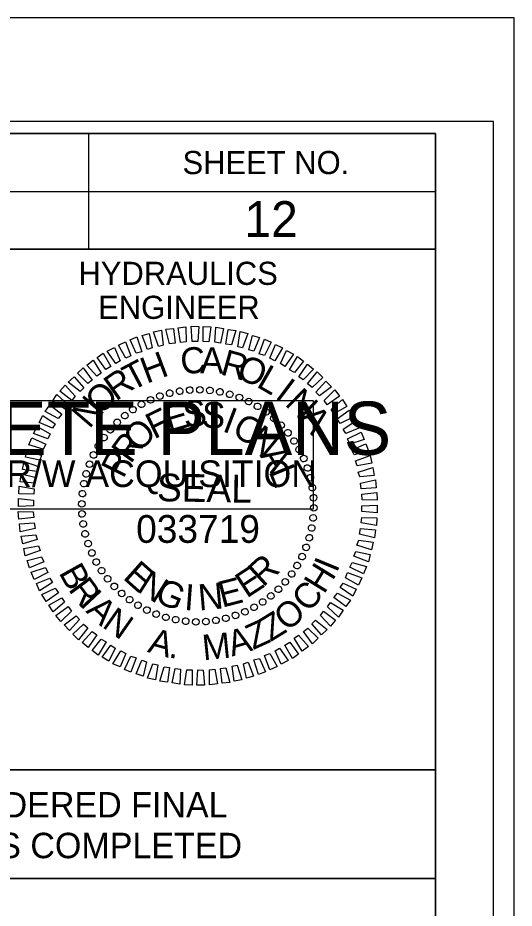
# Model space of a CAD drawing. Extents: x 1779926 to 1781610, y 620464 to 621564.
# Drawn here: x 1781502.7 to 1781610, y 621371.7 to 621564.2 of the extents above; entities that cross this region are included whole.
import ezdxf

# ---------------------------------------------------------------- set-up
doc = ezdxf.new("R2010")
doc.units = 0
for name, color, linetype in [('Old_Level_58', 7, 'Continuous'), ('Sheet Cutting Line CELL', 7, 'Continuous'), ('Sheet Data Field CELL', 7, 'Continuous'), ('Sheet Plot Border Inside CELL', 7, 'Continuous'), ('Sheet Plot Border Outside CELL', 7, 'Continuous'), ('Sheet Professional Seal CELL', 7, 'Continuous'), ('Sheet Profile CELL', 7, 'Continuous'), ('Sheet Profile Grid Major CELL', 7, 'Continuous'), ('Sheet Profile Grid Minor CELL', 7, 'Continuous'), ('Sheet Sticker Exception Certification CELL', 7, 'Continuous'), ('Sheet Sticker Incomplete CELL', 7, 'Continuous')]:
    doc.layers.add(name, color=color, linetype=linetype)

msp = doc.modelspace()

# ---------------------------------------------------------------- linework, layer by layer
at = {"layer": 'Old_Level_58'}
msp.add_lwpolyline([(1781392.96, 621378.14), (1781592.95, 621378.14), (1781592.95, 621314.19), (1781392.96, 621314.19)], close=True, dxfattribs=at)
at = {"layer": 'Sheet Cutting Line CELL'}
msp.add_line((1781609.96, 621564.19), (1779925.96, 621564.19), dxfattribs=at)
at = {"layer": 'Sheet Plot Border Inside CELL'}
msp.add_lwpolyline([(1779938.96, 620486.64), (1781605.46, 620486.64), (1781605.46, 621541.74), (1779938.96, 621541.74)], close=True, dxfattribs=at)
at = {"layer": 'Sheet Plot Border Outside CELL'}
msp.add_lwpolyline([(1779925.96, 620464.19), (1781609.96, 620464.19), (1781609.96, 621564.19), (1779925.96, 621564.19)], close=True, dxfattribs=at)
at = {"layer": 'Sheet Professional Seal CELL'}
for p, q in [((1781533.36, 621482.44), (1781533.36, 621482.44)), ((1781535.46, 621483.04), (1781535.46, 621483.04)), ((1781537.66, 621483.44), (1781537.66, 621483.44)), ((1781539.81, 621483.74), (1781539.81, 621483.74)), ((1781542.01, 621483.79), (1781542.01, 621483.79)), ((1781544.21, 621483.64), (1781544.21, 621483.64)), ((1781546.36, 621483.29), (1781546.36, 621483.29)), ((1781548.46, 621482.84), (1781548.46, 621482.84)), ((1781529.41, 621480.64), (1781529.41, 621480.64)), ((1781531.36, 621481.64), (1781531.36, 621481.64)), ((1781550.56, 621482.14), (1781550.56, 621482.14)), ((1781552.56, 621481.24), (1781552.56, 621481.24)), ((1781527.51, 621479.49), (1781527.51, 621479.49)), ((1781554.51, 621480.24), (1781554.51, 621480.24)), ((1781556.31, 621478.99), (1781556.31, 621478.99)), ((1781524.11, 621476.74), (1781524.11, 621476.74)), ((1781525.76, 621478.24), (1781525.76, 621478.24)), ((1781558.06, 621477.64), (1781558.06, 621477.64)), ((1781522.61, 621475.19), (1781522.61, 621475.19)), ((1781559.61, 621476.14), (1781559.61, 621476.14)), ((1781521.26, 621473.44), (1781521.26, 621473.44)), ((1781561.11, 621474.49), (1781561.11, 621474.49)), ((1781520.01, 621471.64), (1781520.01, 621471.64)), ((1781562.36, 621472.74), (1781562.36, 621472.74)), ((1781519.01, 621469.69), (1781519.01, 621469.69)), ((1781563.51, 621470.84), (1781563.51, 621470.84)), ((1781518.11, 621467.69), (1781518.11, 621467.69)), ((1781564.51, 621468.89), (1781564.51, 621468.89)), ((1781517.41, 621465.59), (1781517.41, 621465.59)), ((1781565.31, 621466.89), (1781565.31, 621466.89)), ((1781516.96, 621463.49), (1781516.96, 621463.49)), ((1781565.91, 621464.79), (1781565.91, 621464.79)), ((1781516.61, 621461.34), (1781516.61, 621461.34)), ((1781566.31, 621462.59), (1781566.31, 621462.59)), ((1781566.61, 621460.44), (1781566.61, 621460.44)), ((1781516.46, 621459.14), (1781516.46, 621459.14)), ((1781541.56, 621458.69), (1781541.56, 621458.69)), ((1781566.66, 621458.24), (1781566.66, 621458.24)), ((1781516.51, 621456.94), (1781516.51, 621456.94)), ((1781566.51, 621456.04), (1781566.51, 621456.04)), ((1781516.81, 621454.79), (1781516.81, 621454.79)), ((1781566.16, 621453.89), (1781566.16, 621453.89)), ((1781517.21, 621452.59), (1781517.21, 621452.59)), ((1781565.71, 621451.79), (1781565.71, 621451.79)), ((1781517.81, 621450.49), (1781517.81, 621450.49)), ((1781565.01, 621449.69), (1781565.01, 621449.69)), ((1781518.61, 621448.49), (1781518.61, 621448.49)), ((1781519.61, 621446.54), (1781519.61, 621446.54)), ((1781564.11, 621447.69), (1781564.11, 621447.69)), ((1781520.76, 621444.64), (1781520.76, 621444.64)), ((1781561.86, 621443.94), (1781561.86, 621443.94)), ((1781563.11, 621445.74), (1781563.11, 621445.74)), ((1781522.01, 621442.89), (1781522.01, 621442.89)), ((1781560.51, 621442.19), (1781560.51, 621442.19)), ((1781523.51, 621441.24), (1781523.51, 621441.24)), ((1781559.01, 621440.64), (1781559.01, 621440.64)), ((1781525.06, 621439.74), (1781525.06, 621439.74)), ((1781526.81, 621438.39), (1781526.81, 621438.39)), ((1781557.36, 621439.14), (1781557.36, 621439.14)), ((1781528.61, 621437.14), (1781528.61, 621437.14)), ((1781553.71, 621436.74), (1781553.71, 621436.74)), ((1781555.61, 621437.89), (1781555.61, 621437.89)), ((1781530.56, 621436.14), (1781530.56, 621436.14)), ((1781532.56, 621435.24), (1781532.56, 621435.24)), ((1781534.66, 621434.54), (1781534.66, 621434.54)), ((1781547.66, 621434.34), (1781547.66, 621434.34)), ((1781549.76, 621434.94), (1781549.76, 621434.94)), ((1781551.76, 621435.74), (1781551.76, 621435.74)), ((1781536.76, 621434.09), (1781536.76, 621434.09)), ((1781538.91, 621433.74), (1781538.91, 621433.74)), ((1781541.11, 621433.59), (1781541.11, 621433.59)), ((1781543.31, 621433.64), (1781543.31, 621433.64)), ((1781545.46, 621433.94), (1781545.46, 621433.94))]:
    msp.add_line(p, q, dxfattribs=at)
for points in [[(1781530.66, 621492.49), (1781529.51, 621495.49), (1781531.06, 621495.94), (1781531.71, 621492.84)], [(1781533.06, 621493.14), (1781532.01, 621496.29), (1781533.71, 621496.64), (1781534.11, 621493.39)], [(1781535.46, 621493.69), (1781534.66, 621496.89), (1781536.31, 621497.04), (1781536.66, 621493.84)], [(1781537.86, 621493.99), (1781537.31, 621497.19), (1781539.01, 621497.39), (1781539.06, 621494.14)], [(1781540.36, 621494.24), (1781540.11, 621497.49), (1781541.76, 621497.44), (1781541.56, 621494.19)], [(1781542.76, 621494.19), (1781542.76, 621497.44), (1781544.41, 621497.39), (1781543.96, 621494.14)], [(1781545.26, 621494.04), (1781545.46, 621497.29), (1781547.11, 621496.99), (1781546.46, 621493.84)], [(1781547.66, 621493.64), (1781548.11, 621496.84), (1781549.76, 621496.59), (1781548.86, 621493.49)], [(1781550.21, 621493.09), (1781550.71, 621496.34), (1781552.41, 621495.94), (1781551.26, 621492.84)], [(1781526.01, 621490.64), (1781524.41, 621493.44), (1781525.96, 621494.14), (1781527.11, 621491.09)], [(1781528.21, 621491.69), (1781526.91, 621494.59), (1781528.41, 621495.19), (1781529.46, 621491.99)], [(1781552.61, 621492.44), (1781553.36, 621495.54), (1781554.91, 621495.04), (1781553.66, 621492.09)], [(1781554.86, 621491.54), (1781556.01, 621494.69), (1781557.41, 621494.09), (1781556.01, 621491.19)], [(1781523.86, 621489.44), (1781522.01, 621492.14), (1781523.56, 621492.94), (1781524.81, 621490.04)], [(1781557.11, 621490.59), (1781558.36, 621493.54), (1781559.91, 621492.84), (1781558.21, 621490.04)], [(1781559.41, 621489.44), (1781560.76, 621492.29), (1781562.26, 621491.44), (1781560.36, 621488.84)], [(1781519.76, 621486.69), (1781517.61, 621489.09), (1781518.96, 621490.14), (1781520.71, 621487.34)], [(1781521.66, 621488.19), (1781519.81, 621490.74), (1781521.11, 621491.69), (1781522.76, 621488.79)], [(1781561.36, 621488.09), (1781563.11, 621490.99), (1781564.41, 621489.94), (1781562.46, 621487.49)], [(1781517.76, 621485.14), (1781515.56, 621487.34), (1781516.76, 621488.54), (1781518.71, 621485.84)], [(1781563.41, 621486.59), (1781565.26, 621489.34), (1781566.56, 621488.24), (1781564.36, 621485.89)], [(1781516.11, 621483.39), (1781513.56, 621485.44), (1781514.81, 621486.59), (1781516.91, 621484.19)], [(1781565.31, 621485.04), (1781567.36, 621487.64), (1781568.56, 621486.44), (1781566.26, 621484.29)], [(1781514.36, 621481.49), (1781511.76, 621483.44), (1781512.86, 621484.74), (1781515.06, 621482.39)], [(1781567.11, 621483.29), (1781569.26, 621485.64), (1781570.46, 621484.44), (1781567.86, 621482.49)], [(1781512.86, 621479.59), (1781510.16, 621481.29), (1781511.11, 621482.74), (1781513.51, 621480.54)], [(1781568.86, 621481.49), (1781571.16, 621483.74), (1781572.21, 621482.39), (1781569.56, 621480.49)], [(1781511.36, 621477.59), (1781508.56, 621479.09), (1781509.56, 621480.49), (1781512.16, 621478.49)], [(1781570.36, 621479.54), (1781572.81, 621481.64), (1781573.76, 621480.19), (1781570.96, 621478.59)], [(1781571.66, 621477.49), (1781574.31, 621479.39), (1781575.26, 621477.89), (1781572.36, 621476.49)], [(1781510.16, 621475.44), (1781507.31, 621476.69), (1781508.06, 621478.24), (1781510.76, 621476.39)], [(1781572.96, 621475.29), (1781575.76, 621477.04), (1781576.41, 621475.49), (1781573.56, 621474.34)], [(1781509.16, 621473.14), (1781506.06, 621474.29), (1781506.81, 621475.84), (1781509.66, 621474.24)], [(1781508.16, 621470.94), (1781505.06, 621471.84), (1781505.71, 621473.39), (1781508.71, 621471.99)], [(1781573.96, 621473.14), (1781576.91, 621474.64), (1781577.56, 621473.04), (1781574.46, 621472.04)], [(1781574.86, 621470.79), (1781577.91, 621472.09), (1781578.46, 621470.54), (1781575.36, 621469.74)], [(1781507.41, 621468.54), (1781504.31, 621469.19), (1781504.66, 621470.84), (1781507.81, 621469.59)], [(1781575.66, 621468.39), (1781578.86, 621469.54), (1781579.16, 621467.89), (1781576.01, 621467.34)], [(1781506.76, 621466.14), (1781503.66, 621466.54), (1781504.01, 621468.24), (1781507.16, 621467.19)], [(1781506.36, 621463.59), (1781503.16, 621463.89), (1781503.36, 621465.59), (1781506.61, 621464.79)], [(1781576.26, 621465.99), (1781579.41, 621466.94), (1781579.71, 621465.24), (1781576.56, 621464.94)], [(1781576.71, 621463.59), (1781579.96, 621464.29), (1781580.11, 621462.59), (1781576.91, 621462.39)], [(1781506.11, 621461.19), (1781502.86, 621461.29), (1781502.96, 621462.94), (1781506.21, 621462.39)], [(1781577.01, 621461.19), (1781580.26, 621461.59), (1781580.36, 621459.89), (1781577.11, 621459.99)], [(1781506.06, 621458.69), (1781502.81, 621458.54), (1781502.81, 621460.24), (1781506.06, 621459.89)], [(1781506.11, 621456.19), (1781502.86, 621455.79), (1781502.76, 621457.49), (1781506.01, 621457.39)], [(1781577.06, 621458.69), (1781580.31, 621458.84), (1781580.31, 621457.14), (1781577.06, 621457.49)], [(1781577.01, 621456.19), (1781580.26, 621456.09), (1781580.16, 621454.44), (1781576.91, 621454.99)], [(1781506.41, 621453.79), (1781503.16, 621453.09), (1781503.01, 621454.79), (1781506.21, 621454.99)], [(1781576.76, 621453.79), (1781579.96, 621453.49), (1781579.76, 621451.79), (1781576.51, 621452.59)], [(1781506.86, 621451.39), (1781503.71, 621450.44), (1781503.41, 621452.14), (1781506.56, 621452.44)], [(1781507.46, 621448.99), (1781504.26, 621447.84), (1781503.96, 621449.49), (1781507.11, 621450.04)], [(1781576.36, 621451.24), (1781579.46, 621450.84), (1781579.11, 621449.14), (1781575.96, 621450.19)], [(1781575.71, 621448.84), (1781578.81, 621448.19), (1781578.46, 621446.54), (1781575.31, 621447.79)], [(1781508.26, 621446.59), (1781505.21, 621445.29), (1781504.66, 621446.84), (1781507.76, 621447.64)], [(1781574.96, 621446.44), (1781578.06, 621445.54), (1781577.41, 621443.99), (1781574.41, 621445.39)], [(1781509.16, 621444.24), (1781506.21, 621442.74), (1781505.56, 621444.34), (1781508.66, 621445.34)], [(1781573.96, 621444.24), (1781577.06, 621443.09), (1781576.31, 621441.54), (1781573.46, 621443.14)], [(1781510.16, 621442.09), (1781507.36, 621440.34), (1781506.71, 621441.89), (1781509.56, 621443.04)], [(1781511.46, 621439.89), (1781508.81, 621437.99), (1781507.86, 621439.49), (1781510.76, 621440.89)], [(1781572.96, 621441.94), (1781575.81, 621440.69), (1781575.06, 621439.14), (1781572.36, 621440.99)], [(1781512.76, 621437.84), (1781510.31, 621435.74), (1781509.36, 621437.19), (1781512.16, 621438.79)], [(1781571.76, 621439.79), (1781574.56, 621438.29), (1781573.56, 621436.89), (1781570.96, 621438.89)], [(1781514.26, 621435.89), (1781511.96, 621433.64), (1781510.91, 621434.99), (1781513.56, 621436.89)], [(1781570.26, 621437.79), (1781572.96, 621436.09), (1781572.01, 621434.64), (1781569.61, 621436.84)], [(1781516.01, 621434.09), (1781513.86, 621431.74), (1781512.66, 621432.94), (1781515.26, 621434.89)], [(1781568.76, 621435.89), (1781571.36, 621433.94), (1781570.26, 621432.64), (1781568.06, 621434.99)], [(1781517.81, 621432.34), (1781515.76, 621429.74), (1781514.56, 621430.94), (1781516.86, 621433.09)], [(1781567.01, 621433.99), (1781569.56, 621431.94), (1781568.31, 621430.79), (1781566.21, 621433.19)], [(1781519.71, 621430.79), (1781517.86, 621428.04), (1781516.56, 621429.14), (1781518.76, 621431.49)], [(1781563.36, 621430.69), (1781565.51, 621428.29), (1781564.16, 621427.24), (1781562.41, 621430.04)], [(1781565.36, 621432.24), (1781567.56, 621430.04), (1781566.36, 621428.84), (1781564.41, 621431.54)], [(1781521.76, 621429.29), (1781520.01, 621426.39), (1781518.71, 621427.44), (1781520.66, 621429.89)], [(1781523.71, 621427.94), (1781522.36, 621425.09), (1781520.86, 621425.94), (1781522.76, 621428.54)], [(1781561.46, 621429.19), (1781563.31, 621426.64), (1781562.01, 621425.69), (1781560.36, 621428.59)], [(1781526.01, 621426.79), (1781524.76, 621423.84), (1781523.21, 621424.54), (1781524.91, 621427.34)], [(1781557.11, 621426.74), (1781558.71, 621423.94), (1781557.16, 621423.24), (1781556.01, 621426.29)], [(1781559.26, 621427.94), (1781561.11, 621425.24), (1781559.56, 621424.44), (1781558.31, 621427.34)], [(1781528.26, 621425.84), (1781527.11, 621422.69), (1781525.71, 621423.29), (1781527.11, 621426.19)], [(1781530.51, 621424.94), (1781529.76, 621421.84), (1781528.21, 621422.34), (1781529.46, 621425.29)], [(1781552.46, 621424.89), (1781553.61, 621421.89), (1781552.06, 621421.44), (1781551.41, 621424.54)], [(1781554.91, 621425.69), (1781556.21, 621422.79), (1781554.71, 621422.19), (1781553.66, 621425.39)], [(1781532.91, 621424.29), (1781532.41, 621421.04), (1781530.71, 621421.44), (1781531.86, 621424.54)], [(1781535.46, 621423.74), (1781535.01, 621420.54), (1781533.36, 621420.79), (1781534.26, 621423.89)], [(1781537.86, 621423.34), (1781537.66, 621420.09), (1781536.01, 621420.39), (1781536.66, 621423.54)], [(1781540.36, 621423.19), (1781540.36, 621419.94), (1781538.71, 621419.99), (1781539.16, 621423.24)], [(1781542.76, 621423.14), (1781543.01, 621419.89), (1781541.36, 621419.94), (1781541.56, 621423.19)], [(1781545.26, 621423.39), (1781545.81, 621420.19), (1781544.11, 621419.99), (1781544.06, 621423.24)], [(1781547.66, 621423.69), (1781548.46, 621420.49), (1781546.81, 621420.34), (1781546.46, 621423.54)], [(1781550.06, 621424.24), (1781551.11, 621421.09), (1781549.41, 621420.74), (1781549.01, 621423.99)]]:
    msp.add_lwpolyline(points, close=True, dxfattribs=at)
for centre, major_axis in [((1781539.81, 621483.71), (-0.05, 0.718)), ((1781542, 621483.77), (0.013, 0.72)), ((1781544.18, 621483.63), (0.075, 0.716)), ((1781531.36, 621481.6), (-0.293, 0.658)), ((1781533.39, 621482.4), (-0.234, 0.681)), ((1781535.49, 621483.03), (-0.174, 0.699)), ((1781537.64, 621483.46), (-0.113, 0.711)), ((1781546.34, 621483.31), (0.137, 0.707)), ((1781548.47, 621482.8), (0.198, 0.692)), ((1781550.55, 621482.1), (0.258, 0.672)), ((1781529.4, 621480.63), (-0.349, 0.63)), ((1781552.55, 621481.23), (0.316, 0.647)), ((1781554.48, 621480.19), (0.371, 0.617)), ((1781525.78, 621478.18), (-0.453, 0.56)), ((1781527.53, 621479.48), (-0.403, 0.597)), ((1781556.3, 621478.98), (0.423, 0.582)), ((1781524.14, 621476.73), (-0.5, 0.518)), ((1781558.01, 621477.62), (0.472, 0.543)), ((1781559.6, 621476.11), (0.518, 0.5)), ((1781522.63, 621475.14), (-0.543, 0.472)), ((1781561.05, 621474.47), (0.56, 0.453)), ((1781521.27, 621473.43), (-0.582, 0.423)), ((1781562.35, 621472.71), (0.597, 0.403)), ((1781520.06, 621471.61), (-0.617, 0.371)), ((1781563.49, 621470.85), (0.63, 0.349)), ((1781519.02, 621469.68), (-0.647, 0.316)), ((1781564.47, 621468.89), (0.658, 0.293)), ((1781518.15, 621467.68), (-0.672, 0.258)), ((1781565.27, 621466.86), (0.681, 0.234)), ((1781517.45, 621465.6), (-0.692, 0.198)), ((1781565.89, 621464.76), (0.699, 0.174)), ((1781516.94, 621463.48), (-0.707, 0.137)), ((1781566.33, 621462.61), (0.711, 0.113)), ((1781516.62, 621461.31), (-0.716, 0.075)), ((1781516.48, 621459.13), (-0.72, 0.013)), ((1781566.58, 621460.44), (0.718, 0.05)), ((1781516.54, 621456.94), (-0.718, -0.05)), ((1781566.64, 621458.25), (0.72, -0.013)), ((1781516.79, 621454.77), (-0.711, -0.113)), ((1781566.5, 621456.07), (0.716, -0.075)), ((1781566.18, 621453.9), (0.707, -0.137)), ((1781517.22, 621452.62), (-0.699, -0.174)), ((1781565.67, 621451.78), (0.692, -0.198)), ((1781517.85, 621450.52), (-0.681, -0.234)), ((1781564.97, 621449.7), (0.672, -0.258)), ((1781518.65, 621448.49), (-0.658, -0.293)), ((1781564.1, 621447.7), (0.647, -0.316)), ((1781519.62, 621446.53), (-0.63, -0.349)), ((1781563.06, 621445.77), (0.617, -0.371)), ((1781520.77, 621444.67), (-0.597, -0.403)), ((1781561.85, 621443.95), (0.582, -0.423)), ((1781522.07, 621442.91), (-0.56, -0.453)), ((1781523.52, 621441.27), (-0.518, -0.5)), ((1781560.49, 621442.24), (0.543, -0.472)), ((1781525.11, 621439.76), (-0.472, -0.543)), ((1781558.98, 621440.65), (0.5, -0.518)), ((1781526.82, 621438.4), (-0.423, -0.582)), ((1781555.58, 621437.9), (0.403, -0.597)), ((1781557.34, 621439.2), (0.453, -0.56)), ((1781528.64, 621437.19), (-0.371, -0.617)), ((1781530.56, 621436.15), (-0.316, -0.647)), ((1781551.76, 621435.78), (0.293, -0.658)), ((1781553.72, 621436.75), (0.349, -0.63)), ((1781532.57, 621435.28), (-0.258, -0.672)), ((1781534.65, 621434.58), (-0.198, -0.692)), ((1781536.77, 621434.07), (-0.137, -0.707)), ((1781538.94, 621433.75), (-0.075, -0.716)), ((1781541.12, 621433.61), (-0.013, -0.72)), ((1781543.31, 621433.67), (0.05, -0.718)), ((1781545.48, 621433.92), (0.113, -0.711)), ((1781547.63, 621434.36), (0.174, -0.699)), ((1781549.72, 621434.98), (0.234, -0.681))]:
    msp.add_ellipse(centre, major_axis=major_axis, ratio=0.999708, dxfattribs=at)
at = {"layer": 'Sheet Profile CELL'}
for p, q in [((1781517.96, 621539.14), (1781517.96, 621514.14)), ((1781392.91, 621526.64), (1781592.96, 621526.64))]:
    msp.add_line(p, q, dxfattribs=at)
for points in [[(1781592.96, 621539.19), (1780092.96, 621539.19), (1780092.96, 620489.19), (1781592.96, 620489.19)], [(1781392.91, 621539.19), (1781592.96, 621539.19), (1781592.96, 621514.14), (1781392.91, 621514.14)], [(1781492.96, 621514.14), (1781592.96, 621514.14), (1781592.96, 621401.64), (1781492.96, 621401.64)]]:
    msp.add_lwpolyline(points, close=True, dxfattribs=at)
at = {"layer": 'Sheet Profile Grid Major CELL'}
msp.add_lwpolyline([(1781542.96, 621314.19), (1781542.96, 621039.19), (1781592.96, 621039.19), (1781592.96, 621389.19)], dxfattribs=at)
at = {"layer": 'Sheet Sticker Exception Certification CELL'}
for p, q in [((1781392.91, 621401.64), (1781592.95, 621401.64)), ((1781392.91, 621401.64), (1781592.95, 621401.64)), ((1781592.95, 621401.63), (1781592.95, 621378.13)), ((1781592.95, 621401.63), (1781592.95, 621378.13)), ((1781592.95, 621378.14), (1781392.91, 621378.14)), ((1781592.95, 621378.14), (1781392.91, 621378.14))]:
    msp.add_line(p, q, dxfattribs=at)
at = {"layer": 'Sheet Sticker Incomplete CELL'}
msp.add_lwpolyline([(1781419.48, 621457.99), (1781419.48, 621481.49), (1781566.48, 621481.49), (1781566.48, 621457.99)], close=True, dxfattribs=at)

# ---------------------------------------------------------------- texts
at = {"layer": 'Sheet Data Field CELL'}
msp.add_text('12', height=7.75, dxfattribs=at).set_placement((1781551.66, 621516.8))
at = {"layer": 'Sheet Professional Seal CELL'}
for s, height, rotation, p in [('C', 5.64, 6.2199, (1781538.11, 621487.04)), ('A', 5.64, 359.0203, (1781542.06, 621487.34)), ('R', 5.64, 344.6211, (1781546.26, 621487.14)), ('T', 5.64, 27.8198, (1781527.26, 621483.39)), ('H', 5.64, 20.6195, (1781530.51, 621485.04)), ('O', 5.64, 337.4212, (1781549.61, 621486.39)), ('L', 5.64, 330.2209, (1781554.01, 621484.54)), ('R', 5.64, 35.0205, (1781523.86, 621481.19)), ('O', 5.64, 42.2217, (1781520.41, 621478.09)), ('I', 5.64, 323.0201, (1781558.06, 621482.14)), ('N', 5.64, 49.4235, (1781518.11, 621475.19)), ('N', 5.64, 315.8189, (1781560.21, 621480.59)), ('E', 5.64, 16.6111, (1781535.31, 621474.49)), ('S', 5.64, 7.2556, (1781538.76, 621475.54)), ('S', 5.64, 357.9004, (1781542.36, 621475.59)), ('F', 5.64, 25.967, (1781532.11, 621472.99)), ('I', 5.64, 339.1896, (1781546.66, 621474.89)), ('A', 5.64, 308.6172, (1781563.16, 621477.64)), ('O', 5.64, 44.6812, (1781528.81, 621470.04)), ('O', 5.64, 329.8335, (1781548.66, 621474.19)), ('N', 5.64, 320.4766, (1781552.01, 621472.19)), ('R', 5.64, 54.0397, (1781527.06, 621467.59)), ('P', 5.64, 63.3989, (1781525.46, 621464.39)), ('A', 5.64, 301.7603, (1781554.86, 621469.59)), ('L', 5.64, 292.4008, (1781556.81, 621466.14)), ('SEAL', 5.998, 359, (1781532.71, 621459.69)), ('R', 5.64, 42.4814, (1781555.66, 621440.94)), ('E', 5.64, 318.2769, (1781525.16, 621443.04)), ('N', 5.64, 327.634, (1781528.16, 621440.34)), ('E', 5.64, 33.1241, (1781552.11, 621438.59)), ('G', 5.64, 336.9902, (1781531.96, 621438.09)), ('N', 5.64, 5.0564, (1781541.86, 621436.04)), ('E', 5.64, 14.4118, (1781546.81, 621436.64)), ('I', 5.64, 355.7012, (1781538.51, 621436.19))]:
    msp.add_text(s, height=height, rotation=rotation, dxfattribs=at).set_placement(p)
at = {"layer": 'Sheet Profile CELL'}
for s, p in [('SHEET NO.', (1781538.27, 621530.4)), ('HYDRAULICS', (1781515.77, 621506.45)), ('ENGINEER', (1781520.02, 621499.1))]:
    msp.add_text(s, height=5, dxfattribs=at).set_placement(p)
at = {"layer": 'Sheet Profile Grid Minor CELL'}
msp.add_text('033719', height=5.998, dxfattribs=at).set_placement((1781528.24, 621450.68))
for s, rotation, p in [('B', 299.1529, (1781511.41, 621444.25)), ('H', 58.3478, (1781568.87, 621439.42)), ('I', 67.5926, (1781571.61, 621444.05)), ('R', 306.2797, (1781513.44, 621440.62)), ('C', 49.4751, (1781565.57, 621435.43)), ('I', 313.2061, (1781515.82, 621437.36)), ('A', 316.7266, (1781517.18, 621435.82)), ('O', 38.7706, (1781560.83, 621431.38)), ('N', 324.9124, (1781520.68, 621432.58)), ('Z', 31.6438, (1781557.3, 621429.2)), ('Z', 24.517, (1781553.52, 621427.47)), ('A', 344.2893, (1781530.53, 621427.13)), ('M', 5.6554, (1781542.78, 621425.28)), ('A', 16.3312, (1781548.95, 621426.09)), ('.', 352.4751, (1781535.13, 621425.89))]:
    msp.add_text(s, height=5.5, rotation=rotation, dxfattribs=at).set_placement(p)
at = {"layer": 'Sheet Sticker Exception Certification CELL'}
for s, p in [('DOCUMENT NOT CONSIDERED FINAL', (1781413.98, 621391.3)), ('DOCUMENT NOT CONSIDERED FINAL', (1781413.98, 621391.3)), ('UNLESS ALL SIGNATURES COMPLETED', (1781408.91, 621382.5)), ('UNLESS ALL SIGNATURES COMPLETED', (1781408.91, 621382.5))]:
    msp.add_text(s, height=5.5, dxfattribs=at).set_placement(p)
at = {"layer": 'Sheet Sticker Incomplete CELL'}
for s, height, p in [('INCOMPLETE PLANS', 11.52, (1781428.43, 621469.69)), ('DO NOT USE FOR R/W ACQUISITION', 5.76, (1781431.68, 621462.74))]:
    msp.add_text(s, height=height, dxfattribs=at).set_placement(p)

doc.saveas('drawing.dxf')
